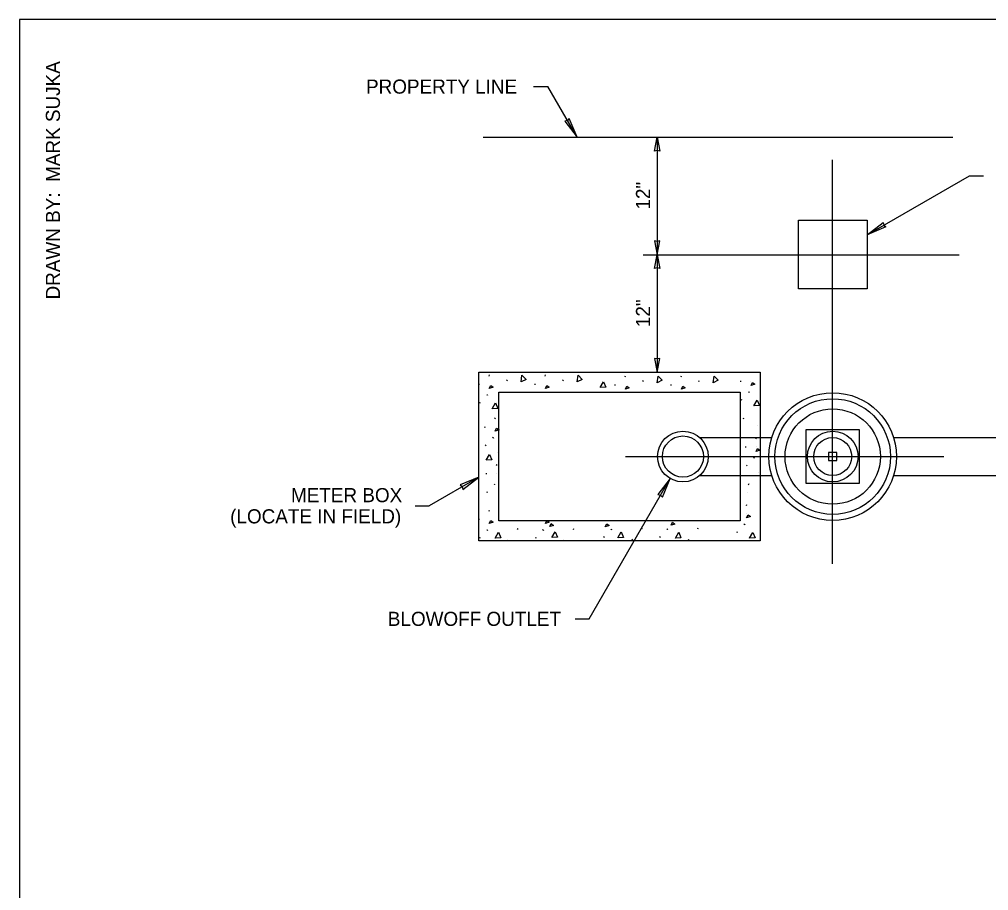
# Model space of a CAD drawing. Extents: x 99862 to 103151, y 99999 to 102075.
# Drawn here: x 99862 to 100960, y 101089 to 102075 of the extents above; entities that cross this region are included whole.
import ezdxf

# ---------------------------------------------------------------- set-up
doc = ezdxf.new("R2010")
doc.units = 0
for name, color, linetype in [('Level 1', 7, 'Continuous'), ('Level 11', 7, 'Continuous'), ('Level 15', 7, 'Continuous'), ('Level 17', 7, 'Continuous'), ('Level 20', 7, 'Continuous'), ('Level 6', 7, 'Continuous'), ('Level 62', 7, 'Continuous')]:
    doc.layers.add(name, color=color, linetype=linetype)

msp = doc.modelspace()

# ---------------------------------------------------------------- linework, layer by layer
at = {"layer": 'Level 1'}
for p, q in [((100394.1, 101671.6), (100394.7, 101672.8)), ((100457.7, 101671.6), (100458.1, 101672.8)), ((100548.2, 101670.7), (100548.8, 101672)), ((100611.7, 101670.7), (100612.2, 101672)), ((100382.4, 101662.9), (100382.5, 101661.8)), ((100414.2, 101666.2), (100414.9, 101667.4)), ((100445.9, 101662.9), (100445.9, 101661.8)), ((100477.8, 101666.2), (100478.3, 101667.4)), ((100536.4, 101662.1), (100536.6, 101660.9)), ((100568.2, 101665.3), (100569, 101666.6)), ((100599.9, 101662.1), (100599.9, 101660.9)), ((100631.9, 101665.3), (100632.3, 101666.6)), ((100678.9, 101666.1), (100679, 101665)), ((100690.8, 101665.9), (100690.8, 101665.9)), ((100391.4, 101650.8), (100391.9, 101650.1)), ((100391.9, 101650.5), (100392.4, 101649.8)), ((100688, 101654), (100688.4, 101653.3)), ((100688.4, 101653.7), (100688.9, 101653)), ((100383.5, 101641), (100384.1, 101642.1)), ((100680, 101644.2), (100680.6, 101645.3)), ((100693.5, 101637.3), (100693.5, 101637.3)), ((100400.8, 101623), (100401.4, 101624.2)), ((100682.3, 101623), (100682.8, 101624.2)), ((100389, 101614.3), (100389.2, 101613.2)), ((100697.7, 101615.4), (100697.7, 101615.4)), ((100398.1, 101602.2), (100398.6, 101601.5)), ((100398.6, 101601.9), (100399.1, 101601.2)), ((100390.2, 101592.4), (100390.8, 101593.5)), ((100684.7, 101591.6), (100684.8, 101590.5)), ((100696.5, 101600.3), (100697, 101601.5)), ((100696.6, 101591.4), (100696.6, 101591.4)), ((100403.7, 101585.4), (100403.7, 101585.4)), ((100402.5, 101570.3), (100403.1, 101571.5)), ((100685.8, 101569.7), (100686.4, 101570.8)), ((100693.8, 101579.5), (100694.2, 101578.8)), ((100694.2, 101579.2), (100694.7, 101578.5)), ((100390.7, 101561.6), (100390.9, 101560.5)), ((100402.6, 101561.4), (100402.6, 101561.4)), ((100699.3, 101562.7), (100699.3, 101562.7)), ((100399.8, 101549.5), (100400.2, 101548.8)), ((100400.2, 101549.3), (100400.8, 101548.6)), ((100688.1, 101548.4), (100688.7, 101549.7)), ((100391.9, 101539.7), (100392.4, 101540.9)), ((100686.8, 101540.1), (100686.8, 101540.1)), ((100405.4, 101532.8), (100405.4, 101532.8)), ((100685.6, 101524.9), (100686.2, 101526.2)), ((100394.1, 101518.5), (100394.7, 101519.7)), ((100685.7, 101516.1), (100685.7, 101516.1)), ((100382.4, 101509.8), (100382.5, 101508.7)), ((100682.9, 101504.2), (100683.3, 101503.5)), ((100683.3, 101503.9), (100683.9, 101503.2)), ((100391.4, 101497.7), (100391.9, 101497)), ((100391.9, 101497.4), (100392.4, 101496.7)), ((100426.3, 101497.7), (100427, 101499)), ((100454.8, 101497.7), (100455.4, 101497)), ((100455.4, 101497.4), (100455.8, 101496.7)), ((100489.9, 101497.7), (100490.3, 101499)), ((100532.2, 101498.5), (100532.6, 101497.8)), ((100532.6, 101498.3), (100533.2, 101497.6)), ((100567, 101498.5), (100567.7, 101499.8)), ((100595.6, 101498.5), (100596.1, 101497.8)), ((100596.1, 101498.3), (100596.6, 101497.6)), ((100630.7, 101498.5), (100631.1, 101499.8)), ((100675, 101494.4), (100675.6, 101495.5)), ((100383.5, 101487.9), (100384.1, 101489)), ((100415.6, 101484.9), (100416.2, 101486.1)), ((100447, 101487.9), (100447.6, 101489)), ((100479.1, 101484.9), (100479.5, 101486.1)), ((100524.2, 101488.7), (100524.8, 101489.9)), ((100556.3, 101485.8), (100556.9, 101486.9)), ((100587.7, 101488.7), (100588.3, 101489.9)), ((100619.9, 101485.8), (100620.3, 101486.9)), ((100688.5, 101487.4), (100688.5, 101487.4))]:
    msp.add_line(p, q, dxfattribs=at)
msp.add_lwpolyline([(99862, 99999.5), (103151, 99999.5), (103151, 102075.5), (99862, 102075.5)], close=True, dxfattribs=at)
for points in [[(100430.4, 101664.9), (100431.4, 101672.4), (100436.2, 101667.6), (100430.5, 101664.9)], [(100493.9, 101664.9), (100494.9, 101672.4), (100499.7, 101667.6), (100494, 101664.9)], [(100584.4, 101664), (100585.5, 101671.6), (100590.3, 101666.8), (100584.6, 101664)], [(100648, 101664), (100649, 101671.6), (100653.8, 101666.8), (100648.1, 101664)], [(100394.4, 101657.6), (100396, 101661), (100398.7, 101659), (100394.4, 101657.6)], [(100457.9, 101657.6), (100459.5, 101661), (100462.1, 101659), (100457.9, 101657.6)], [(100520.1, 101658.5), (100523.6, 101665.2), (100526.3, 101659), (100520.2, 101658.5)], [(100548.5, 101656.8), (100550.1, 101660.2), (100552.7, 101658.2), (100548.5, 101656.8)], [(100612, 101656.8), (100613.6, 101660.2), (100616.2, 101658.2), (100612, 101656.8)], [(100691, 101660.8), (100692.5, 101664.3), (100695.2, 101662.3), (100691, 101660.8)], [(100397.7, 101634.5), (100401.3, 101641.1), (100404.1, 101634.9), (100397.9, 101634.5)], [(100694.2, 101637.7), (100697.8, 101644.4), (100700.6, 101638.1), (100694.4, 101637.7)], [(100401.1, 101609), (100402.7, 101612.4), (100405.4, 101610.5), (100401.1, 101609)], [(100391, 101576.3), (100394.6, 101582.9), (100397.4, 101576.7), (100391.2, 101576.3)], [(100696.8, 101586.3), (100698.3, 101589.7), (100701, 101587.7), (100696.8, 101586.3)], [(100685.9, 101511), (100687.5, 101514.4), (100690.2, 101512.4), (100685.9, 101511)], [(100394.4, 101504.5), (100396, 101507.9), (100398.7, 101506), (100394.4, 101504.5)], [(100457.9, 101504.5), (100459.5, 101507.9), (100462.1, 101506), (100457.9, 101504.5)], [(100463, 101501), (100464.5, 101504.4), (100467.1, 101502.4), (100463, 101501)], [(100525.8, 101500.8), (100527.4, 101504.2), (100530, 101502.2), (100525.8, 101500.8)], [(100600.4, 101502.5), (100601.9, 101505.9), (100604.5, 101503.9), (100600.4, 101502.5)], [(100401, 101487.9), (100404.6, 101494.6), (100407.5, 101488.3), (100401.2, 101487.9)], [(100465.2, 101488.6), (100468.8, 101495.2), (100471.5, 101489), (100465.4, 101488.6)], [(100540.1, 101488.4), (100543.7, 101495.1), (100546.5, 101488.8), (100540.3, 101488.4)], [(100605.3, 101488.1), (100608.9, 101494.8), (100611.5, 101488.5), (100605.4, 101488.1)], [(100689.2, 101487.9), (100692.8, 101494.5), (100695.6, 101488.3), (100689.3, 101487.9)]]:
    msp.add_lwpolyline(points, dxfattribs=at)
at = {"layer": 'Level 11'}
msp.add_lwpolyline([(100744.5, 101848), (100822.3, 101848), (100822.3, 101770.2), (100744.5, 101770.2)], close=True, dxfattribs=at)
at = {"layer": 'Level 15'}
for p, q in [((100444.6, 101999.4), (100460.6, 101999.4)), ((100493.8, 101942), (100460.6, 101999.4)), ((100387.4, 101942), (100919.6, 101942)), ((100584.5, 101942), (100584.5, 101809)), ((100783.3, 101458.8), (100783.3, 101916.6)), ((100822.3, 101831.6), (100938.2, 101898.5)), ((100938.2, 101898.5), (100954.2, 101898.5)), ((100568.5, 101809), (100926.7, 101809)), ((100584.5, 101809), (100584.5, 101675.9)), ((100548.6, 101580.5), (100909.4, 101580.5)), ((100382.5, 101557.2), (100326.2, 101524.7)), ((100507.6, 101396.6), (100599.3, 101555.6)), ((100310.2, 101524.7), (100326.2, 101524.7)), ((100491.6, 101396.6), (100507.6, 101396.6))]:
    msp.add_line(p, q, dxfattribs=at)
for points in [[(100493.8, 101942), (100484.9, 101963.3), (100482.9, 101960.9), (100479.8, 101960.3)], [(100584.5, 101942), (100587.6, 101926.3), (100584.5, 101927), (100581.4, 101926.3)], [(100822.3, 101831.6), (100840.6, 101845.6), (100841.2, 101842.5), (100843.6, 101840.4)], [(100584.5, 101809), (100587.6, 101824.7), (100584.5, 101824), (100581.4, 101824.7)], [(100584.5, 101809), (100587.6, 101793.3), (100584.5, 101794), (100581.4, 101793.3)], [(100584.5, 101675.9), (100587.6, 101691.6), (100584.5, 101690.9), (100581.4, 101691.6)], [(100382.5, 101557.2), (100361.3, 101548.3), (100363.7, 101546.3), (100364.3, 101543.2)], [(100599.3, 101555.6), (100585.3, 101537.3), (100588.5, 101536.7), (100590.5, 101534.3)]]:
    msp.add_lwpolyline(points, close=True, dxfattribs=at)
at = {"layer": 'Level 17'}
for p, q in [((100382.5, 101485), (100382.5, 101675.9)), ((100382.5, 101675.9), (100701.1, 101675.9)), ((100701.1, 101675.9), (100701.1, 101485)), ((100405.2, 101507.6), (100405.2, 101653.3)), ((100405.2, 101653.3), (100678.5, 101653.3)), ((100678.5, 101653.3), (100678.5, 101507.6)), ((100678.5, 101507.6), (100405.2, 101507.6)), ((100701.1, 101485), (100382.5, 101485))]:
    msp.add_line(p, q, dxfattribs=at)
at = {"layer": 'Level 6'}
for p, q in [((100632.6, 101602), (100678.5, 101602)), ((100678.5, 101602), (100701.1, 101602)), ((100701.1, 101602), (100714.3, 101602)), ((100852.4, 101602), (101254.6, 101602)), ((100632.6, 101558.9), (100678.5, 101558.9)), ((100678.5, 101558.9), (100701.1, 101558.9)), ((100701.1, 101558.9), (100714.3, 101558.9)), ((100852.4, 101558.9), (101254.2, 101558.9))]:
    msp.add_line(p, q, dxfattribs=at)
for points in [[(100753.1, 101610.6), (100753.1, 101550.3), (100813.8, 101550.3), (100813.8, 101610.6)], [(100787.9, 101585.1), (100778.6, 101585.1), (100778.6, 101575.8), (100787.9, 101575.8)]]:
    msp.add_lwpolyline(points, close=True, dxfattribs=at)
for centre, radius in [((100783.4, 101580.4), 72.3), ((100783.4, 101580.4), 65.5), ((100783.4, 101580.4), 54), ((100613.7, 101580.4), 28.7), ((100613.7, 101580.4), 23.3), ((100783.4, 101580.4), 28.7), ((100783.4, 101580.4), 21.5)]:
    msp.add_circle(centre, radius, dxfattribs=at)

# ---------------------------------------------------------------- texts
at = {"layer": 'Level 20'}
for s, p in [('PROPERTY LINE', (100254.7, 101991.4)), ('METER BOX', (100169.7, 101528.7)), ('(LOCATE IN FIELD)', (100100.8, 101504.7)), ('BLOWOFF OUTLET', (100279.4, 101388.6))]:
    msp.add_text(s, height=16, dxfattribs=at).set_placement(p)
for p in [(100576.5, 101860.1), (100576.5, 101727)]:
    msp.add_text('12"', height=16, rotation=90, dxfattribs=at).set_placement(p)
at = {"layer": 'Level 62'}
msp.add_text('DRAWN BY:  MARK SUJKA', height=16, rotation=90, dxfattribs=at).set_placement((99908, 101758.3))

doc.saveas('drawing.dxf')
